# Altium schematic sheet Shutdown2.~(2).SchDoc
size A4
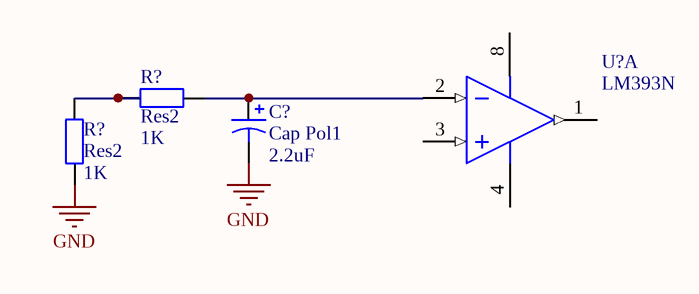
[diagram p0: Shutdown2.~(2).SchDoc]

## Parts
(Parts that share a designator on the sheet are numbered #1, #2 ... from top to bottom, then left to right.)
C?  Cap Pol1  value 2.2uF  [RB7.6-15]
R?#1  Res2  value 1K  [AXIAL-0.4]
R?#2  Res2  value 1K  [AXIAL-0.4]
U?  LM393N  [626-05]  (part A of 2)

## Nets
GND: C?.2 R?#2.1
NetC?_1: C?.1 R?#1.2 U?.2(IN-)
NetR?#1_1: R?#1.1 R?#2.2

Not connected (* = marked no-connect by the designer): U? 1(OUT) 3(IN+) 4(GND) 8(V+)

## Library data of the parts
C? = Cap Pol1: Polarized Capacitor (Radial)
R?#1 R?#2 = Res2: Resistor
U? = LM393N: Dual Comparator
